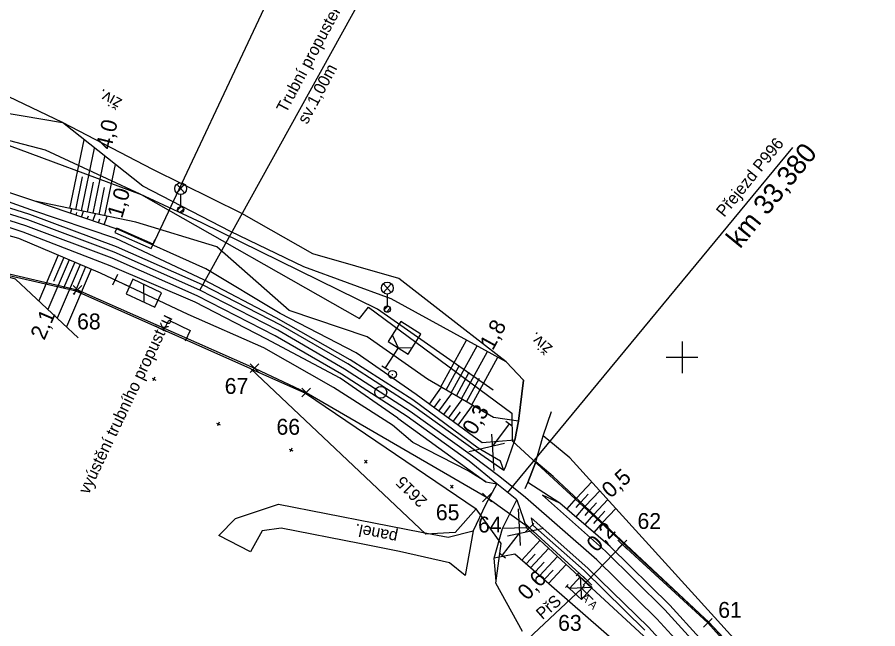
# Model space of a CAD drawing. Extents: x -805011 to -803920, y -1150790 to -1150234.
# Drawn here: x -804283.8 to -804175.3, y -1150534.3 to -1150457.1 of the extents above; entities that cross this region are included whole.
import ezdxf

# ---------------------------------------------------------------- set-up
doc = ezdxf.new("R2010")
doc.units = 0
for name, color, linetype in [('0381KM032-037P - Vrstva 1', 7, 'Continuous'), ('0381KM032-037P - Vrstva 17', 7, 'Continuous'), ('0381KM032-037P - Vrstva 19', 7, 'Continuous'), ('0381KM032-037P - Vrstva 25', 7, 'Continuous'), ('0381KM032-037P - Vrstva 4', 7, 'Continuous'), ('0381KM032-037P - Vrstva 43', 7, 'Continuous'), ('0381KM032-037P - Vrstva 48', 7, 'Continuous'), ('0381KM032-037P - Vrstva 49', 7, 'Continuous'), ('0381KM032-037P - Vrstva 51', 7, 'Continuous'), ('0381KM032-037P - Vrstva 55', 7, 'Continuous'), ('0381KM032-037P - Vrstva 57', 7, 'Continuous'), ('0381KM032-037P - Vrstva 6', 7, 'Continuous'), ('0381KM032-037P - Vrstva 7', 7, 'Continuous'), ('0381KM032-037P - Vrstva 9', 7, 'Continuous'), ('Default', 7, 'Continuous'), ('hran DP - hran DP', 7, 'Continuous'), ('krizky_1000 - Vrstva 1', 7, 'Continuous'), ('PSR_C2_2_Lomove_body_Vimperk - Vrstva 60', 7, 'Continuous'), ('PSR_C2_2_trasa_Vimperk - Kabelová trasa', 7, 'Continuous')]:
    doc.layers.add(name, color=color, linetype=linetype)

msp = doc.modelspace()

# ---------------------------------------------------------------- linework, layer by layer
at = {"layer": '0381KM032-037P - Vrstva 1'}
for points in [[(-804222.98, -1150515.09), (-804226.42, -1150512.48), (-804234.26, -1150506.83), (-804242.54, -1150501.49), (-804250.96, -1150496.61), (-804260.8, -1150491.55), (-804271.59, -1150486.76), (-804282.48, -1150482.69), (-804291.53, -1150479.85), (-804302.34, -1150477.08), (-804311.51, -1150475.27), (-804320.67, -1150473.88), (-804330.92, -1150472.81), (-804341.55, -1150472.27), (-804345.19, -1150472.22)], [(-804170.82, -1150577.3), (-804176.26, -1150567.85), (-804182.37, -1150558.45), (-804188.8, -1150549.63), (-804195.8, -1150541.09), (-804203.2, -1150532.98), (-804210.73, -1150525.57), (-804219.76, -1150517.68), (-804222.98, -1150515.09)]]:
    msp.add_lwpolyline(points, dxfattribs=at)
at = {"layer": '0381KM032-037P - Vrstva 17'}
msp.add_lwpolyline([(-804223.8, -1150504.14), (-804238.39, -1150493.96), (-804260.56, -1150483.05), (-804280.24, -1150473.89), (-804302.47, -1150468.07)], dxfattribs=at)
at = {"layer": '0381KM032-037P - Vrstva 19'}
msp.add_line((-804260.8, -1150491.55), (-804226.07, -1150428.82), dxfattribs=at)
at = {"layer": '0381KM032-037P - Vrstva 25'}
for p, q in [((-804263.7, -1150478.18), (-804262.71, -1150479.29)), ((-804263.69, -1150479.31), (-804262.71, -1150478.19)), ((-804263.21, -1150479.49), (-804263.21, -1150480.99)), ((-804263.6, -1150481.47), (-804263.13, -1150481)), ((-804263.33, -1150481.77), (-804262.83, -1150481.27)), ((-804237.65, -1150490.73), (-804236.66, -1150491.84)), ((-804237.64, -1150491.86), (-804236.66, -1150490.74)), ((-804237.16, -1150492.04), (-804237.16, -1150493.54)), ((-804237.55, -1150494.02), (-804237.08, -1150493.55)), ((-804237.28, -1150494.32), (-804236.78, -1150493.82))]:
    msp.add_line(p, q, dxfattribs=at)
for centre, radius in [((-804263.21, -1150478.74), 0.749), ((-804263.21, -1150481.39), 0.4), ((-804263.21, -1150481.39), 0.4), ((-804237.16, -1150491.29), 0.749), ((-804237.16, -1150493.94), 0.4), ((-804237.16, -1150493.94), 0.4)]:
    msp.add_circle(centre, radius, dxfattribs=at)
at = {"layer": '0381KM032-037P - Vrstva 4'}
for p, q in [((-804186.06, -1150473.54), (-804222.06, -1150517.12)), ((-804221.8, -1150508.42), (-804223.88, -1150511.23)), ((-804221.4, -1150508.72), (-804222.2, -1150508.12)), ((-804223.68, -1150514.31), (-804224, -1150509.71)), ((-804222.4, -1150510.9), (-804226.89, -1150511.93)), ((-804219.76, -1150517.68), (-804222.98, -1150515.09)), ((-804220.66, -1150519.13), (-804220.42, -1150523.73)), ((-804222, -1150522.51), (-804217.49, -1150521.57)), ((-804222.65, -1150524.98), (-804220.51, -1150522.21)), ((-804223.05, -1150524.67), (-804222.25, -1150525.29))]:
    msp.add_line(p, q, dxfattribs=at)
for points in [[(-804225.7, -1150511.47), (-804233.93, -1150505.38), (-804241.84, -1150500.35), (-804251.18, -1150495.03), (-804260.27, -1150490.25), (-804271.39, -1150485.02), (-804282.1, -1150481.42), (-804291.28, -1150478.15), (-804302, -1150475.62), (-804311.22, -1150473.82), (-804320.47, -1150472.35), (-804331.17, -1150471.28), (-804341.36, -1150470.84), (-804345.11, -1150470.79), (-804355.15, -1150471.09), (-804364.49, -1150471.64), (-804373.72, -1150472.46), (-804382.56, -1150473.46), (-804390.64, -1150474.3), (-804394.58, -1150474.82), (-804430.68, -1150479.4), (-804471.16, -1150484.87), (-804515.79, -1150490.21)], [(-804222.47, -1150514.31), (-804225.93, -1150511.88), (-804233.81, -1150506.22), (-804242.12, -1150500.85), (-804250.57, -1150495.96), (-804260.44, -1150490.89), (-804271.28, -1150486.07), (-804282.21, -1150481.99), (-804291.28, -1150479.14), (-804302.11, -1150476.36), (-804311.33, -1150474.54), (-804320.55, -1150473.14), (-804330.83, -1150472.06), (-804341.5, -1150471.52), (-804345.16, -1150471.47), (-804355.1, -1150471.64), (-804364.39, -1150472.17), (-804373.73, -1150473.02), (-804382.33, -1150473.97), (-804390.45, -1150474.97), (-804394.45, -1150475.48), (-804430.79, -1150480.07), (-804470.48, -1150485.06), (-804515.61, -1150490.8)], [(-804223.37, -1150515.97), (-804226.85, -1150513.1), (-804234.67, -1150507.48), (-804242.93, -1150502.16), (-804251.31, -1150497.29), (-804261.13, -1150492.25), (-804271.85, -1150487.49), (-804282.71, -1150483.42), (-804291.73, -1150480.59), (-804302.46, -1150477.85), (-804311.66, -1150476.01), (-804320.71, -1150474.65), (-804330.94, -1150473.58), (-804341.55, -1150473.05), (-804345.16, -1150472.99), (-804355.02, -1150473.16), (-804364.28, -1150473.69), (-804373.57, -1150474.51), (-804382.12, -1150475.46), (-804390.26, -1150476.46), (-804394.25, -1150476.96), (-804430.61, -1150481.56), (-804470.33, -1150486.56), (-804515.43, -1150492.3)], [(-804235.83, -1150507.71), (-804243.11, -1150502.63), (-804252.43, -1150497.68), (-804261.4, -1150493.06), (-804272.11, -1150488.47), (-804283.06, -1150484.22), (-804291.82, -1150481.32), (-804302.89, -1150478.85), (-804311.92, -1150476.81), (-804320.92, -1150475.47), (-804331.06, -1150474.34), (-804341.56, -1150473.81), (-804345.45, -1150473.75), (-804355.04, -1150473.96), (-804364.32, -1150474.45), (-804373.64, -1150475.34), (-804382.1, -1150476.35), (-804390.24, -1150477.29), (-804394.24, -1150477.85), (-804430.45, -1150482.3), (-804470.19, -1150487.36), (-804515.37, -1150493.06)], [(-804235.83, -1150507.71), (-804224.74, -1150515.72), (-804223.37, -1150515.97)], [(-804222.47, -1150514.31), (-804222.91, -1150513.11), (-804225.7, -1150511.47)], [(-804187.11, -1150547.91), (-804194.06, -1150539.52), (-804201.53, -1150531.26), (-804209.07, -1150523.88), (-804215.39, -1150518.4), (-804217.61, -1150517.41)], [(-804187.68, -1150548.56), (-804194.64, -1150540.13), (-804202.18, -1150531.87), (-804209.67, -1150524.48), (-804217.61, -1150517.41)], [(-804190.06, -1150550.44), (-804196.91, -1150542.06), (-804204.25, -1150534.03), (-804211.9, -1150526.62), (-804219.04, -1150520.28), (-804218.83, -1150521.2), (-804212.36, -1150526.9), (-804204.69, -1150534.44)]]:
    msp.add_lwpolyline(points, dxfattribs=at)
at = {"layer": '0381KM032-037P - Vrstva 43'}
msp.add_lwpolyline([(-804265.36, -1150496.69), (-804264.71, -1150495.33), (-804262, -1150496.62), (-804262.65, -1150497.98)], dxfattribs=at)
at = {"layer": '0381KM032-037P - Vrstva 48'}
for p, q in [((-804277.17, -1150481.25), (-804275.39, -1150472.58)), ((-804275.7, -1150481.55), (-804274.07, -1150473.62)), ((-804274.23, -1150481.85), (-804272.76, -1150474.67)), ((-804272.76, -1150482.15), (-804271.44, -1150475.71)), ((-804276.44, -1150481.4), (-804275.58, -1150477.25)), ((-804274.97, -1150481.7), (-804274.19, -1150477.92)), ((-804273.5, -1150482), (-804272.8, -1150478.59)), ((-804277.11, -1150481.85), (-804276.92, -1150481.3)), ((-804276.4, -1150482.09), (-804276.29, -1150481.77)), ((-804275.69, -1150482.33), (-804275.44, -1150481.6)), ((-804274.27, -1150482.81), (-804273.96, -1150481.91)), ((-804274.98, -1150482.57), (-804274.84, -1150482.16)), ((-804273.56, -1150483.05), (-804273.39, -1150482.55)), ((-804272.85, -1150483.29), (-804272.48, -1150482.21)), ((-804278.64, -1150487.13), (-804281.11, -1150492.91)), ((-804277.95, -1150487.43), (-804279.23, -1150490.44)), ((-804277.26, -1150487.72), (-804279.94, -1150494)), ((-804275.88, -1150488.31), (-804278.78, -1150495.09)), ((-804276.57, -1150488.02), (-804277.96, -1150491.28)), ((-804274.5, -1150488.9), (-804277.61, -1150496.19)), ((-804275.19, -1150488.6), (-804276.69, -1150492.12)), ((-804230.4, -1150503.75), (-804227.17, -1150497.84)), ((-804229.1, -1150504.51), (-804225.85, -1150498.56)), ((-804227.81, -1150505.26), (-804224.53, -1150499.28)), ((-804226.51, -1150506.02), (-804223.22, -1150500)), ((-804229.75, -1150504.13), (-804228.13, -1150501.17)), ((-804228.45, -1150504.88), (-804226.82, -1150501.9)), ((-804227.16, -1150505.64), (-804225.52, -1150502.64)), ((-804231.86, -1150505.91), (-804230.32, -1150503.8)), ((-804230.65, -1150506.79), (-804229.01, -1150504.56)), ((-804231.26, -1150506.35), (-804230.46, -1150505.26)), ((-804229.44, -1150507.68), (-804227.71, -1150505.32)), ((-804230.05, -1150507.24), (-804229.2, -1150506.09)), ((-804228.84, -1150508.12), (-804227.95, -1150506.91)), ((-804228.23, -1150508.57), (-804226.41, -1150506.08)), ((-804213.32, -1150517.78), (-804211.39, -1150515.72)), ((-804213.34, -1150517.77), (-804214.53, -1150519.14)), ((-804212.77, -1150518.3), (-804211.83, -1150517.29)), ((-804212.22, -1150518.81), (-804210.38, -1150516.84)), ((-804212.24, -1150518.79), (-804213.4, -1150520.12)), ((-804212.79, -1150518.28), (-804213.38, -1150518.96)), ((-804211.68, -1150519.32), (-804210.78, -1150518.36)), ((-804211.13, -1150519.83), (-804209.37, -1150517.95)), ((-804211.7, -1150519.3), (-804212.27, -1150519.96)), ((-804211.15, -1150519.82), (-804212.27, -1150521.11)), ((-804210.58, -1150520.35), (-804209.72, -1150519.43)), ((-804210.04, -1150520.86), (-804208.36, -1150519.07)), ((-804210.6, -1150520.33), (-804211.15, -1150520.97)), ((-804210.05, -1150520.84), (-804211.13, -1150522.09)), ((-804220.22, -1150525.59), (-804217.9, -1150523.08)), ((-804219.09, -1150526.57), (-804216.8, -1150524.1)), ((-804219.66, -1150526.08), (-804218.5, -1150524.83)), ((-804217.96, -1150527.56), (-804215.7, -1150525.12)), ((-804218.53, -1150527.07), (-804217.39, -1150525.84)), ((-804216.83, -1150528.54), (-804214.6, -1150526.14)), ((-804217.39, -1150528.05), (-804216.27, -1150526.84))]:
    msp.add_line(p, q, dxfattribs=at)
at = {"layer": '0381KM032-037P - Vrstva 49'}
for p, q in [((-804266.48, -1150502.54), (-804266.7, -1150503)), ((-804266.82, -1150502.66), (-804266.36, -1150502.88)), ((-804258.7, -1150508.31), (-804258.24, -1150508.53)), ((-804258.36, -1150508.19), (-804258.58, -1150508.65)), ((-804220.62, -1150508.07), (-804221.1, -1150510.47)), ((-804218.43, -1150513.19), (-804217.51, -1150509.9)), ((-804214.14, -1150512.69), (-804217.51, -1150509.9)), ((-804249.54, -1150511.61), (-804249.08, -1150511.83)), ((-804249.2, -1150511.49), (-804249.42, -1150511.95)), ((-804239.68, -1150513.36), (-804240.04, -1150513)), ((-804239.68, -1150513), (-804240.04, -1150513.36)), ((-804218.43, -1150513.19), (-804219.46, -1150515.79)), ((-804216.26, -1150515.03), (-804218.43, -1150513.19)), ((-804224.74, -1150515.72), (-804226.97, -1150514.32)), ((-804228.85, -1150516.15), (-804229.21, -1150516.51)), ((-804229.21, -1150516.15), (-804228.85, -1150516.51)), ((-804220.84, -1150517.99), (-804219.6, -1150521.51)), ((-804219.6, -1150521.51), (-804222.65, -1150521.62)), ((-804221.09, -1150524.83), (-804223.68, -1150525.36))]:
    msp.add_line(p, q, dxfattribs=at)
for points in [[(-804320.34, -1150463.27), (-804278.12, -1150470.41)], [(-804221.1, -1150510.47), (-804225.19, -1150510.8), (-804233.52, -1150504.69), (-804241.09, -1150499.46), (-804250.66, -1150494.51), (-804260.04, -1150488.87), (-804271.07, -1150483.89), (-804281.58, -1150480.34), (-804290.68, -1150477.29), (-804301.47, -1150474.53), (-804310.76, -1150472.67), (-804320.3, -1150471.51), (-804330.99, -1150470.46), (-804340.83, -1150469.83), (-804345.1, -1150470.19), (-804354.95, -1150469.89)], [(-804222.18, -1150500.57), (-804236.67, -1150492.64), (-804247.69, -1150488.59), (-804256.93, -1150484.13), (-804267.99, -1150478.45), (-804278.12, -1150470.41)], [(-804226.97, -1150514.32), (-804233.94, -1150510.78), (-804236.52, -1150508.57), (-804243.93, -1150503.82), (-804252.72, -1150498.82), (-804262.25, -1150494.6), (-804273.33, -1150489.4), (-804283.59, -1150485.01), (-804292.89, -1150482.47), (-804303.02, -1150479.68), (-804312.2, -1150478.16), (-804321.12, -1150476.62), (-804331.14, -1150475.24), (-804341.8, -1150475.06), (-804345.41, -1150474.87), (-804355.14, -1150475.34), (-804364.22, -1150475.73), (-804373.58, -1150476.33), (-804382.14, -1150477.38), (-804390.01, -1150478.23), (-804394.36, -1150478.78), (-804430.35, -1150482.91), (-804470.16, -1150488.05), (-804515.21, -1150493.93)], [(-804276.15, -1150497.56), (-804284.03, -1150490.16), (-804299.15, -1150485.83), (-804306.89, -1150483.98), (-804317.28, -1150482.7), (-804327.05, -1150481.84), (-804338.6, -1150481.41), (-804350.55, -1150480.59), (-804360.54, -1150481.11), (-804374.96, -1150483.29), (-804385.39, -1150485.41), (-804391.71, -1150485.5), (-804430.73, -1150489.32), (-804470.3, -1150492.85), (-804514.17, -1150497.56)], [(-804220.62, -1150508.07), (-804223.76, -1150507.62), (-804232.08, -1150502.77), (-804239.7, -1150497.43), (-804249.53, -1150494.12), (-804258.64, -1150486.1), (-804268.88, -1150482.95), (-804281.58, -1150480.34)], [(-804222.18, -1150500.57), (-804220.01, -1150502.88), (-804220.62, -1150508.07)], [(-804179.78, -1150547.3), (-804187.89, -1150541.65), (-804195.9, -1150532.8), (-804214.14, -1150512.69)], [(-804216.26, -1150515.03), (-804196.49, -1150533.54), (-804188.66, -1150542.31), (-804183.72, -1150548.22), (-804177, -1150556.4), (-804165.66, -1150573.06), (-804155.49, -1150590.5), (-804146.45, -1150604.86), (-804136.37, -1150622.31), (-804131.91, -1150629.82), (-804122.71, -1150645.64), (-804115.71, -1150666.79), (-804102.89, -1150677.06), (-804092.51, -1150687.92), (-804076.71, -1150692.97), (-804062.72, -1150701.97), (-804052.08, -1150706.52)], [(-804220.84, -1150517.99), (-804223.37, -1150515.97), (-804224.79, -1150518.63), (-804226.34, -1150521.9), (-804227.33, -1150527.53)], [(-804194.06, -1150539.52), (-804201.53, -1150531.26), (-804209.07, -1150523.88), (-804215.39, -1150518.4), (-804219.46, -1150515.79)], [(-804223.68, -1150525.36), (-804222.65, -1150521.62), (-804220.84, -1150517.99)], [(-804190.46, -1150550.87), (-804201.54, -1150538.22), (-804219.6, -1150521.51)], [(-804191.88, -1150555.68), (-804193.53, -1150552.03), (-804203.25, -1150540.38), (-804221.09, -1150524.83)]]:
    msp.add_lwpolyline(points, dxfattribs=at)
at = {"layer": '0381KM032-037P - Vrstva 51'}
for points in [[(-804222.47, -1150514.31), (-804222.23, -1150513.73), (-804221.1, -1150510.47), (-804220.62, -1150508.07), (-804220.01, -1150502.88), (-804222.18, -1150500.57), (-804227.38, -1150496.55), (-804235.69, -1150490.06), (-804246.55, -1150486.97), (-804255.48, -1150481.87), (-804266.7, -1150476.32), (-804278.12, -1150470.41), (-804293.62, -1150463)], [(-804219.78, -1150516.58), (-804219.46, -1150515.79), (-804218.43, -1150513.19), (-804217.51, -1150509.9), (-804216.47, -1150506.86)], [(-804223.37, -1150515.97), (-804224.79, -1150518.63), (-804226.34, -1150521.9), (-804227.33, -1150527.53)], [(-804227.33, -1150527.53), (-804229.32, -1150525.92), (-804235.62, -1150524.51), (-804240.66, -1150523.49), (-804250.54, -1150521.55), (-804252.94, -1150521.92), (-804254.39, -1150524.56), (-804258.4, -1150522.49), (-804256.28, -1150520.34), (-804250.86, -1150518.54), (-804232.85, -1150522.07), (-804229.47, -1150522.71), (-804226.34, -1150521.9)], [(-804223.45, -1150528.25), (-804223.68, -1150525.36), (-804222.65, -1150521.62), (-804220.84, -1150517.99)]]:
    msp.add_lwpolyline(points, dxfattribs=at)
at = {"layer": '0381KM032-037P - Vrstva 55'}
msp.add_lwpolyline([(-804254.35, -1150501.48), (-804247.48, -1150504.53), (-804225.97, -1150519.11), (-804228.6, -1150522.11), (-804232.32, -1150522.3)], close=True, dxfattribs=at)
at = {"layer": '0381KM032-037P - Vrstva 6'}
for p, q in [((-804212.64, -1150529.17), (-804242.83, -1150557.41)), ((-804212.29, -1150528.81), (-804212.99, -1150529.53)), ((-804211.21, -1150530.54), (-804212.64, -1150529.17))]:
    msp.add_line(p, q, dxfattribs=at)
at = {"layer": '0381KM032-037P - Vrstva 7'}
for p, q in [((-804271.17, -1150489.56), (-804271.81, -1150490.92)), ((-804267.9, -1150490.82), (-804267.84, -1150493.06)), ((-804235.81, -1150498.82), (-804237.44, -1150501.34)), ((-804237.86, -1150501.07), (-804237.02, -1150501.61)), ((-804236.57, -1150502.17), (-804236.47, -1150502.17)), ((-804213.37, -1150527.56), (-804213.03, -1150527.19)), ((-804212.83, -1150527.71), (-804213.2, -1150527.38)), ((-804214.71, -1150529.04), (-804214.38, -1150528.67)), ((-804212.83, -1150527.71), (-804214.18, -1150529.19)), ((-804212.83, -1150527.71), (-804211.35, -1150529.06)), ((-804212.83, -1150527.71), (-804212.7, -1150530.54)), ((-804214.18, -1150529.19), (-804214.55, -1150528.86)), ((-804211.35, -1150529.06), (-804214.18, -1150529.19)), ((-804214.18, -1150529.19), (-804212.7, -1150530.54)), ((-804211.35, -1150529.06), (-804212.7, -1150530.54))]:
    msp.add_line(p, q, dxfattribs=at)
for points in [[(-804271.49, -1150490.24), (-804269.68, -1150491.09), (-804270.1, -1150491.99), (-804266.48, -1150493.69), (-804265.63, -1150491.88), (-804269.25, -1150490.18), (-804269.68, -1150491.09)], [(-804235.81, -1150498.82), (-804234.55, -1150499.63), (-804232.93, -1150497.11), (-804235.45, -1150495.48), (-804237.07, -1150498.01), (-804235.81, -1150498.82)], [(-804236.53, -1150497.16), (-804235.81, -1150498.82), (-804234.01, -1150498.79)]]:
    msp.add_lwpolyline(points, dxfattribs=at)
for centre, radius in [((-804236.52, -1150502.17), 0.5), ((-804237.98, -1150504.43), 0.75)]:
    msp.add_circle(centre, radius, dxfattribs=at)
at = {"layer": '0381KM032-037P - Vrstva 9'}
for p, q in [((-804237.76, -1150424.25), (-804266.81, -1150486.01)), ((-804271.26, -1150483.71), (-804271.5, -1150484.26)), ((-804266.69, -1150485.74), (-804271.26, -1150483.71)), ((-804271.5, -1150484.26), (-804266.93, -1150486.28)), ((-804266.69, -1150485.74), (-804266.45, -1150485.19)), ((-804266.93, -1150486.28), (-804266.69, -1150485.74))]:
    msp.add_line(p, q, dxfattribs=at)
at = {"layer": 'hran DP - hran DP'}
for p, q in [((-804301.77, -1150466.98), (-804268.19, -1150479.5)), ((-804268.19, -1150479.5), (-804240.65, -1150495.11)), ((-804276.4, -1150491.69), (-804317.89, -1150482.17)), ((-804254.35, -1150501.48), (-804276.4, -1150491.69)), ((-804240.65, -1150495.11), (-804239.52, -1150493.68)), ((-804239.52, -1150493.68), (-804221.47, -1150507.06)), ((-804232.32, -1150522.3), (-804254.35, -1150501.48)), ((-804221.47, -1150507.06), (-804221.41, -1150510.55)), ((-804221.41, -1150510.55), (-804216.71, -1150514.88)), ((-804216.71, -1150514.88), (-804196.65, -1150533.37)), ((-804225.97, -1150519.11), (-804228.6, -1150522.11)), ((-804222.81, -1150523.51), (-804225.97, -1150519.11)), ((-804228.6, -1150522.11), (-804232.32, -1150522.3)), ((-804223.47, -1150528.51), (-804222.81, -1150523.51)), ((-804220.13, -1150534.61), (-804223.47, -1150528.51)), ((-804196.65, -1150533.37), (-804178.11, -1150553.27))]:
    msp.add_line(p, q, dxfattribs=at)
at = {"layer": 'krizky_1000 - Vrstva 1'}
for points in [[(-804200, -1150498), (-804200, -1150502)], [(-804202, -1150500), (-804198, -1150500)]]:
    msp.add_lwpolyline(points, dxfattribs=at)
at = {"layer": 'PSR_C2_2_Lomove_body_Vimperk - Vrstva 60'}
for p, q in [((-804276.76, -1150492.06), (-804275.66, -1150490.96)), ((-804275.66, -1150492.06), (-804276.76, -1150490.96)), ((-804254.44, -1150501.94), (-804253.34, -1150500.84)), ((-804253.34, -1150501.94), (-804254.44, -1150500.84)), ((-804247.94, -1150505.02), (-804246.84, -1150503.92)), ((-804246.84, -1150505.02), (-804247.94, -1150503.92)), ((-804225.14, -1150518.23), (-804224.04, -1150517.13)), ((-804224.04, -1150518.23), (-804225.14, -1150517.13)), ((-804219.79, -1150522.07), (-804218.69, -1150520.97)), ((-804218.69, -1150522.07), (-804219.79, -1150520.97)), ((-804208.08, -1150524.16), (-804206.98, -1150523.06)), ((-804206.98, -1150524.16), (-804208.08, -1150523.06)), ((-804212.49, -1150528.76), (-804211.39, -1150527.66)), ((-804211.39, -1150528.76), (-804212.49, -1150527.66)), ((-804197.32, -1150534.07), (-804196.22, -1150532.97)), ((-804196.22, -1150534.07), (-804197.32, -1150532.97))]:
    msp.add_line(p, q, dxfattribs=at)
at = {"layer": 'PSR_C2_2_trasa_Vimperk - Kabelová trasa'}
for points in [[(-804289, -1150488.51), (-804276.21, -1150491.51), (-804253.89, -1150501.39), (-804247.39, -1150504.47), (-804224.59, -1150517.68), (-804219.24, -1150521.52), (-804211.94, -1150528.21)], [(-804211.94, -1150528.21), (-804207.53, -1150523.61), (-804196.77, -1150533.52), (-804182.83, -1150549.06), (-804177, -1150556.4), (-804170.6, -1150565.5), (-804165.46, -1150573.1), (-804159.32, -1150583.6), (-804148.34, -1150601.45), (-804139.82, -1150616.03), (-804133.21, -1150627.36), (-804121.85, -1150646.68), (-804112.03, -1150660.85), (-804099.51, -1150673.08)]]:
    msp.add_lwpolyline(points, dxfattribs=at)

# ---------------------------------------------------------------- texts
at = {"layer": '0381KM032-037P - Vrstva 19'}
for s, p in [('Trubní propustek zasypán', (-804249.91, -1150469.3)), ('sv.1,00m', (-804247.26, -1150470.71))]:
    msp.add_text(s, height=1.5, rotation=61.9777, dxfattribs=at).set_placement(p)
at = {"layer": '0381KM032-037P - Vrstva 4'}
for s, height, p in [('Přejezd P996', 1.5, (-804194.69, -1150482.43)), ('km 33,380', 2.5, (-804192.7, -1150486.41))]:
    msp.add_text(s, height=height, rotation=50.856, dxfattribs=at).set_placement(p)
at = {"layer": '0381KM032-037P - Vrstva 43'}
msp.add_text('vyústění trubního propustku', height=1.5, rotation=64.5558, dxfattribs=at).set_placement((-804274.83, -1150517.39))
at = {"layer": '0381KM032-037P - Vrstva 48'}
for s, rotation, p in [('4,0', 76.5616, (-804271.98, -1150473.92)), ('1,0', 73.3867, (-804270.6, -1150482.58)), ('2,1', 66.8351, (-804280.4, -1150497.95)), ('1,8', 61.3093, (-804223.87, -1150499.25)), ('0,3', 59.7607, (-804226.12, -1150509.96)), ('0,5', 42.198, (-804209.02, -1150517.88)), ('0,2', 46.8794, (-804210.79, -1150524.7)), ('0,6', 47.212, (-804219.48, -1150530.78))]:
    msp.add_text(s, height=2, rotation=rotation, dxfattribs=at).set_placement(p)
at = {"layer": '0381KM032-037P - Vrstva 51'}
for s, rotation, p in [('živ.', 151.1139, (-804270.48, -1150467.55)), ('živ.', 138.2966, (-804216.22, -1150498.71)), ('panel.', 168.559, (-804235.76, -1150522.06))]:
    msp.add_text(s, height=1.5, rotation=rotation, dxfattribs=at).set_placement(p)
at = {"layer": '0381KM032-037P - Vrstva 57'}
msp.add_text('2615', height=1.5, rotation=135.0206, dxfattribs=at).set_placement((-804232.02, -1150518.03))
at = {"layer": '0381KM032-037P - Vrstva 6'}
for s, height, rotation, p in [('PřS', 1.5, 41.3444, (-804217.6, -1150533.18)), ('  A A ', 1, 316.3444, (-804213.33, -1150529.89))]:
    msp.add_text(s, height=height, rotation=rotation, dxfattribs=at).set_placement(p)
at = {"layer": 'Default'}
for s, p in [('68', (-804276.27, -1150496.49)), ('67', (-804257.66, -1150504.63)), ('66', (-804251.13, -1150509.78)), ('65', (-804231.04, -1150520.56)), ('62', (-804205.62, -1150521.66)), ('64', (-804225.72, -1150522.11)), ('61', (-804195.44, -1150532.87)), ('63', (-804215.63, -1150534.51))]:
    msp.add_text(s, height=2, dxfattribs=at).set_placement(p)

doc.saveas('drawing.dxf')
